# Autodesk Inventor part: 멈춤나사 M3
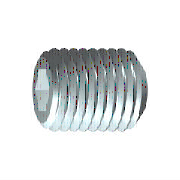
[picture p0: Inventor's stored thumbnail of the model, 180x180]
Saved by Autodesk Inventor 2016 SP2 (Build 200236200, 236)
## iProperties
IsCustomPart: 1
Created: 2012-02
Part Number: 멈춤나사 M3
Material: 강철, 연강
Description: 6각 소켓 머리 없는 멈춤 나사
Document SubType Name: Modeling
Standard: KS B 1028
Designer: mduedu
Standards Organization: KS
Language: ko-KR
Size Designation: 납작점M3x8
Categories: <MemberInstance><Categories><Category DisplayName="조임쇠" InternalName="e4da775c-781d-43d5-af7c-5136215cf5a6" Mnemonic="FSTN"><Category DisplayName="볼트" InternalN
Density: 1 g/cm^3
Appearance: 강철
Author: mduedu
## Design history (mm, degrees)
sketch "스케치1"
  geometry: L1 (0, 0)-(5.5, 0); L2 (8, 0.866)-(8, 1.5); L3 (8, 1.5)-(0, 1.5); L4 (8, 0.866)-(6, 0.866); L5 (6, 0.866)-(5.5, 0); L6 (0, -0.3)-(0, 1.8) reference; L7 (0, 1.5)-(0, 0)
  constraints: 13 end point, 3 parallel, 1 collinear, 1 perpendicular, 1 point on line
  dimensions: "d0" = 2 distance of L2.start L4.end (= INTI); "d1" = 60 deg angle of L5 L1; "d2" = 3 diameter of L3 L1 (= NND); "d3" = 1.73205 diameter of L4 L1 (= 1.1547 x SW); "d5" = 8 distance from line of L2 L3.end (= NLG)
revolve "본체" sketch "스케치1" stored, may be unused: angle "d6" = 90 deg
sketch "스케치2"
  geometry: L1 (-0.433, 0.75)-(0.433, 0.75); L2 (0.433, 0.75)-(0.866, 0); L3 (0.866, 0)-(0.433, -0.75); L4 (0.433, -0.75)-(-0.433, -0.75); L5 (-0.433, -0.75)-(-0.866, 0); L6 (-0.866, 0)-(-0.433, 0.75); A1 r 0.866 centre (0, 0) between (-0.433, 0.75) and (0.433, 0.75) reference; 2 further points
  constraints: 12 end point, 2 point on circle, 1 coincident, 1 horizontal, 11 other
extrude "슬롯" join sketch "스케치2" taper "d9" = 0 deg; stored distance "d21" = 10
workaxis "Work Axis1"
workplane "Work Plane1"
body "Solid1"
chamfer "모따기1" distance "d7" = 0.30673 (= -0.5 x GD1 + 0.5 x NND); stored, may be unused: angle "d8" = 45 deg (= FAWI), second distance "d29" = 0.30673 (= -0.5 x GD1 + 0.5 x NND)
feature "스레드" dims "d11" = 8 (= NLG), "d12" = 0
chamfer "모따기2" distance "d13" = 0.30673 (= -0.5 x GD1 + 0.5 x NND); stored, may be unused: angle "d14" = 45 deg (= FAWI), second distance "d30" = 0.30673 (= -0.5 x GD1 + 0.5 x NND)
other parameters: "NND" = 3 [user parameter; used in 5 equation terms], "NLG" = 8 [user parameter; used in 2 equation terms], "INTI" = 2 [user parameter; used in 1 equation term], "FAWI" = 45 deg [user parameter; used in 2 equation terms], "SW" = 1.5 [user parameter; used in 2 equation terms], "GD1" = 2.38655 (= THREADDIA - 1.2269 x PTC) [user parameter; used in 4 equation terms], "d4" = 0, "FAWI1" = 45 deg [user parameter], "d15" = 0, "d31" = 0, "GUL" = 0.30673 (= 0.61345 x PTC) [user parameter], "SPD" = 2 [user parameter], "TOA" = 30 deg [user parameter], "THREADDIA" = 3 [user parameter; used in 1 equation term], "PTC" = 0.5 [user parameter; used in 4 equation terms], "GAL" = 0.30673 (= 0.61345 x PTC) [user parameter], "E0" = 1.7325 (= 1.155 x SW) [user parameter]
